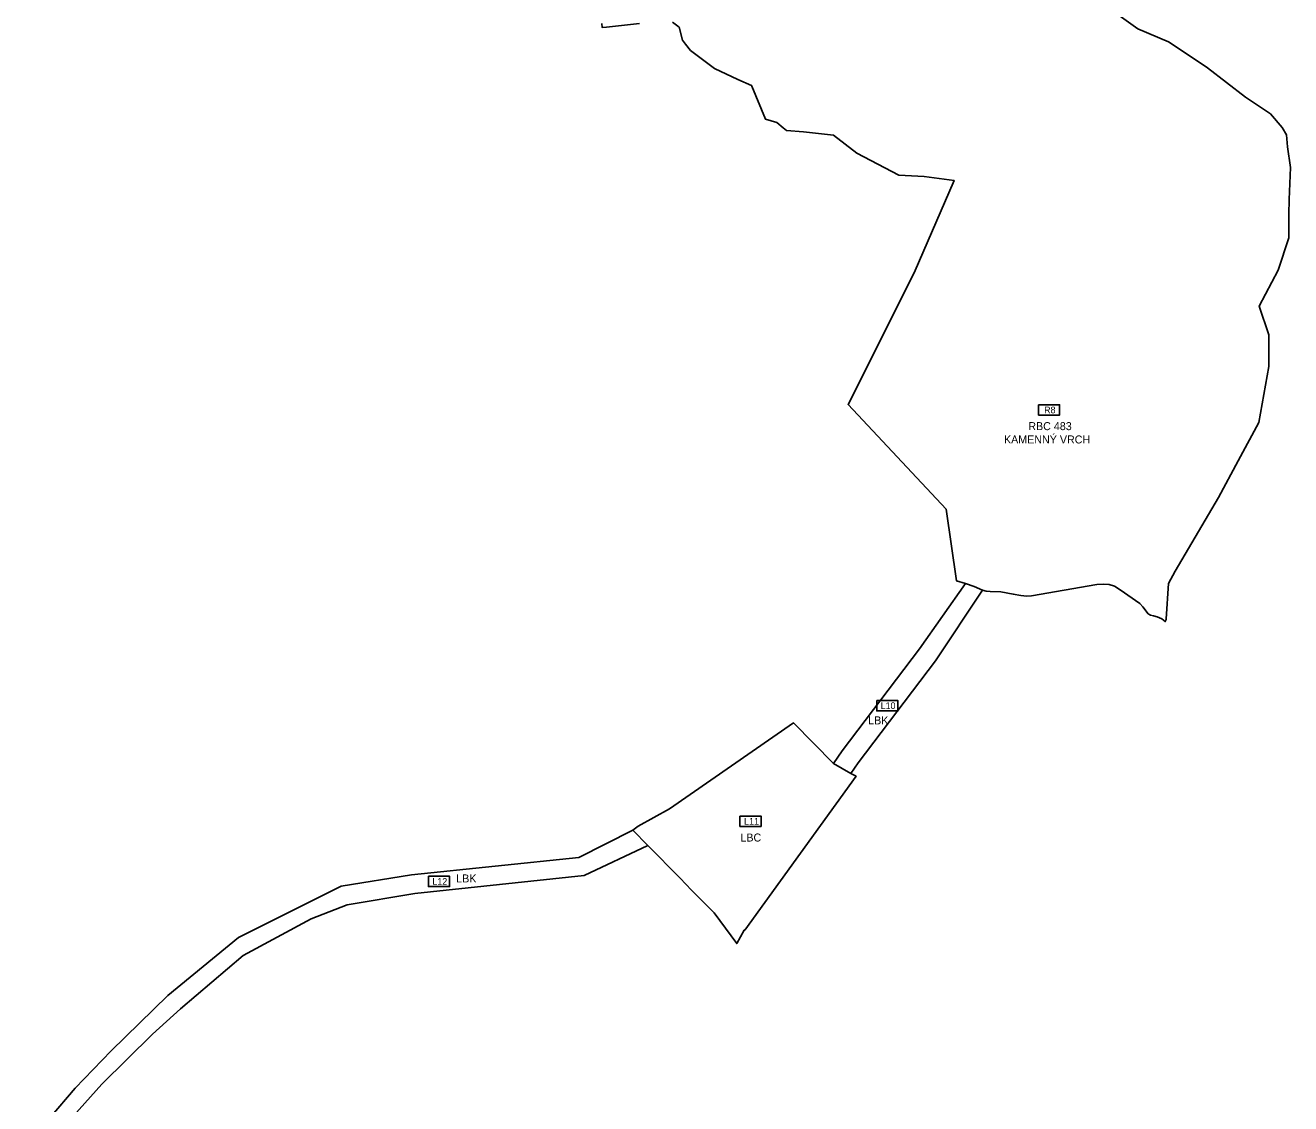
# Model space of a CAD drawing. Extents: x -546680 to -530218, y -1046521 to -1035695.
# Drawn here: x -542332 to -540434, y -1042594 to -1040976 of the extents above; entities that cross this region are included whole.
import ezdxf

# ---------------------------------------------------------------- set-up
doc = ezdxf.new("R2010")
doc.units = 0
for name, color, linetype in [('Vrstva 16', 7, 'Continuous'), ('Vrstva 3', 7, 'Continuous'), ('Vrstva 30', 7, 'Continuous'), ('Vrstva 32', 7, 'Continuous'), ('Vrstva 33', 7, 'Continuous'), ('Vrstva 54', 7, 'Continuous'), ('Vrstva 82', 7, 'Continuous')]:
    doc.layers.add(name, color=color, linetype=linetype)

msp = doc.modelspace()

# ---------------------------------------------------------------- linework, layer by layer
at = {"layer": 'Vrstva 16'}
for points in [[(-540634.1, -1041863.7), (-540627.2, -1041866.5), (-540622.1, -1041870.9), (-540620.8, -1041867.7), (-540620.7, -1041866.5), (-540617.2, -1041813.7), (-540607.4, -1041795), (-540542.4, -1041684.7), (-540512.7, -1041629.5), (-540481.6, -1041572), (-540466.9, -1041488.1), (-540466.7, -1041440.7), (-540481.4, -1041397.5), (-540452.8, -1041343.7), (-540436.6, -1041295), (-540436.6, -1041255.9), (-540436.2, -1041241), (-540436.2, -1041237.7), (-540434.1, -1041189.6), (-540438.6, -1041158.6), (-540440.3, -1041140.5), (-540446.9, -1041129.5), (-540464.2, -1041109.2), (-540501.8, -1041084.2), (-540558.9, -1041039.9), (-540584.7, -1041022.3), (-540617.3, -1041000.7), (-540663.1, -1040981.3), (-540701.9, -1040954.1)], [(-541467.2, -1040973.5), (-541466.9, -1040979.4), (-541460.4, -1040978.7), (-541410.9, -1040973.2)], [(-541361.4, -1040971.4), (-541351.5, -1040979), (-541346.1, -1040998.5), (-541341.8, -1041004.2), (-541334.5, -1041013.9), (-541298.2, -1041041), (-541263.5, -1041057.7), (-541242.7, -1041066.5), (-541242.4, -1041067.3), (-541221.8, -1041117.1), (-541205, -1041121.8), (-541195.2, -1041130), (-541190.3, -1041134.1), (-541165, -1041136), (-541120, -1041141), (-541085, -1041168), (-541022, -1041201), (-540984, -1041203), (-540939, -1041209), (-540998.8, -1041347.7), (-541098, -1041545), (-540951, -1041702), (-540935.4, -1041809.6), (-540921.7, -1041813.6), (-540908.7, -1041818.2), (-540896.1, -1041823.8), (-540890.6, -1041825.1), (-540885, -1041825.8), (-540868.7, -1041826.3), (-540850.1, -1041829.5), (-540838.7, -1041831.8), (-540829.9, -1041832.5), (-540822.6, -1041832), (-540724.9, -1041815.4), (-540715, -1041814.9), (-540706.1, -1041815.4), (-540698.1, -1041817.9), (-540689.8, -1041823), (-540660.5, -1041843.9), (-540655.6, -1041848.6), (-540647.9, -1041859.1), (-540644.4, -1041861.2), (-540639.6, -1041862.3), (-540634.1, -1041863.7)]]:
    msp.add_lwpolyline(points, dxfattribs=at)
at = {"layer": 'Vrstva 30'}
msp.add_lwpolyline([(-540812.3, -1041545.6), (-540812.3, -1041561.1), (-540780.6, -1041561.1), (-540780.6, -1041545.6), (-540812.3, -1041545.6)], dxfattribs=at)
at = {"layer": 'Vrstva 32'}
msp.add_lwpolyline([(-541093.8, -1042098.7), (-541120, -1042084), (-541180, -1042023), (-541366, -1042152), (-541413, -1042178), (-541421, -1042184), (-541398.3, -1042207), (-541350, -1042256), (-541333, -1042274), (-541328, -1042279), (-541299, -1042308), (-541265, -1042354), (-541254, -1042334), (-541253, -1042334), (-541086, -1042103), (-541093.8, -1042098.7)], dxfattribs=at)
at = {"layer": 'Vrstva 33'}
for points in [[(-540908.7, -1041818.2), (-540896.1, -1041823.8), (-540967, -1041930), (-541083, -1042083), (-541093.8, -1042098.7), (-541120, -1042084), (-541107, -1042065), (-540991, -1041912), (-540921.7, -1041813.6), (-540908.7, -1041818.2)], [(-542332, -1042659), (-542257, -1042571), (-542203, -1042515), (-542118, -1042432), (-542012, -1042345), (-541858, -1042268), (-541753, -1042251), (-541502, -1042225), (-541421, -1042184), (-541398.3, -1042207), (-541494, -1042252), (-541748, -1042279), (-541849, -1042296), (-541903, -1042317), (-542005, -1042372), (-542099, -1042452), (-542141, -1042490), (-542217, -1042565), (-542285, -1042641)]]:
    msp.add_lwpolyline(points, dxfattribs=at)
at = {"layer": 'Vrstva 54'}
for points in [[(-541054.9, -1041989.3), (-541054.9, -1042004.9), (-541023.2, -1042004.9), (-541023.2, -1041989.3), (-541054.9, -1041989.3)], [(-541260.2, -1042162.7), (-541260.2, -1042178.2), (-541228.5, -1042178.2), (-541228.5, -1042162.7), (-541260.2, -1042162.7)], [(-541727.3, -1042253), (-541727.3, -1042268.5), (-541695.6, -1042268.5), (-541695.6, -1042253), (-541727.3, -1042253)]]:
    msp.add_lwpolyline(points, dxfattribs=at)

# ---------------------------------------------------------------- texts
at = {"layer": 'Vrstva 3'}
for s, p in [('KAMENNÝ VRCH', (-540864.1, -1041603.6)), ('RBC 483', (-540827.6, -1041583.6)), ('LBK', (-541067.8, -1042025.1)), ('LBC', (-541259.4, -1042200.9)), ('LBK', (-541685.7, -1042262.3))]:
    msp.add_text(s, height=12, dxfattribs=at).set_placement(p)
at = {"layer": 'Vrstva 54'}
for s, p in [('L10', (-541049.1, -1042002.1)), ('L11', (-541253.9, -1042175.5)), ('L12', (-541721.5, -1042265.8))]:
    msp.add_text(s, height=10, dxfattribs=at).set_placement(p)
at = {"layer": 'Vrstva 82'}
msp.add_text('R8', height=10, dxfattribs=at).set_placement((-540803.9, -1041558.3))

doc.saveas('drawing.dxf')
